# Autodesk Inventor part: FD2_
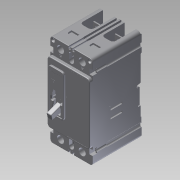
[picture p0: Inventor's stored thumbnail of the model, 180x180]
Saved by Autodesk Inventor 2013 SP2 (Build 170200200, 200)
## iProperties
Created: 2014-08
Part Number: FD2_
Material: Generic
Document SubType Name: Modeling
Designer: DM/JS
Density: 1 g/cm^3
Description: TYPE FD THERMAL MAGNETIC CIRCUIT BREAKERS TWO POLE, SERIES C
Translation Standard: STEP AP214IS
FileName: Y:\ECO-062745\WIP\New\FD2_.stp
PreProcessor: Autodesk Inventor 2012
PostProcessor: Build: 219, Release: 2012 SP2 - Date: Fri 04/27/2012
Sent Units: inch
Uncertainty: 0.00039370078740199997
MXEDIT: false
MXINVTNRV: INV Versioned Component|FD2_|003.0
Author: DM/JS
Revision Number: 003
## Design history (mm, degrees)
node "FD2_"
node "L1"
node "L2"
node "T1"
node "T2"
body "Solid1"
node "Base1"
